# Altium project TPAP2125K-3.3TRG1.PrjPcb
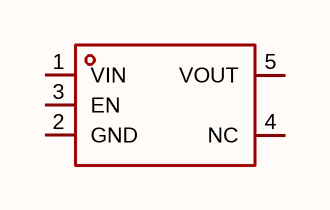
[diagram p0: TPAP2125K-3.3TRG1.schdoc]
1 sheet, 1 parts. Net scope: global (net labels, ports and power ports of the same name join across sheets).

## Sheet TPAP2125K-3.3TRG1.schdoc
size 127 x 101 mm

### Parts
U?  tpap2125k-3.3trg1  [SOT-23-5_L3.0-W1.7-P0.95-LS2.8-BR]  (value not drawn)

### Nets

Not connected (* = marked no-connect by the designer): U? 1(VIN) 2(GND) 3(EN) 4(NC) 5(VOUT)

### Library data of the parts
U? = tpap2125k-3.3trg1: 输出极性:正极;工作电压:7V;输出电压:3.3V;输出电流:300mA;电源纹波抑制比(PSRR):70dB@(1kHz);输出类型:固定;; Manufacturer: TECH PUBLIC(台舟); AddInBom: yes; ModelId: 0a2a1b8f50944f73965918ad6e5fe167; ModelName: SOT-23-5_L2.9-W1.6-H1.1-LS2.8-P0.95; ModelTransform: 114.173,109.636,0,180,0,0,0,0,0; Output Configuration: 正极; Voltage - Supply: 7V; Output Voltage: 3.3V; Output Current: 300mA; standby current: 800nA; Output Type: 固定; Number of Outputs: 1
